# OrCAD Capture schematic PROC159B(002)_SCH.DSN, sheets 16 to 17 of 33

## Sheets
16 29. SOC-ADC & DAC INTERFACE: size C; title: SOC-ADC INTERFACE
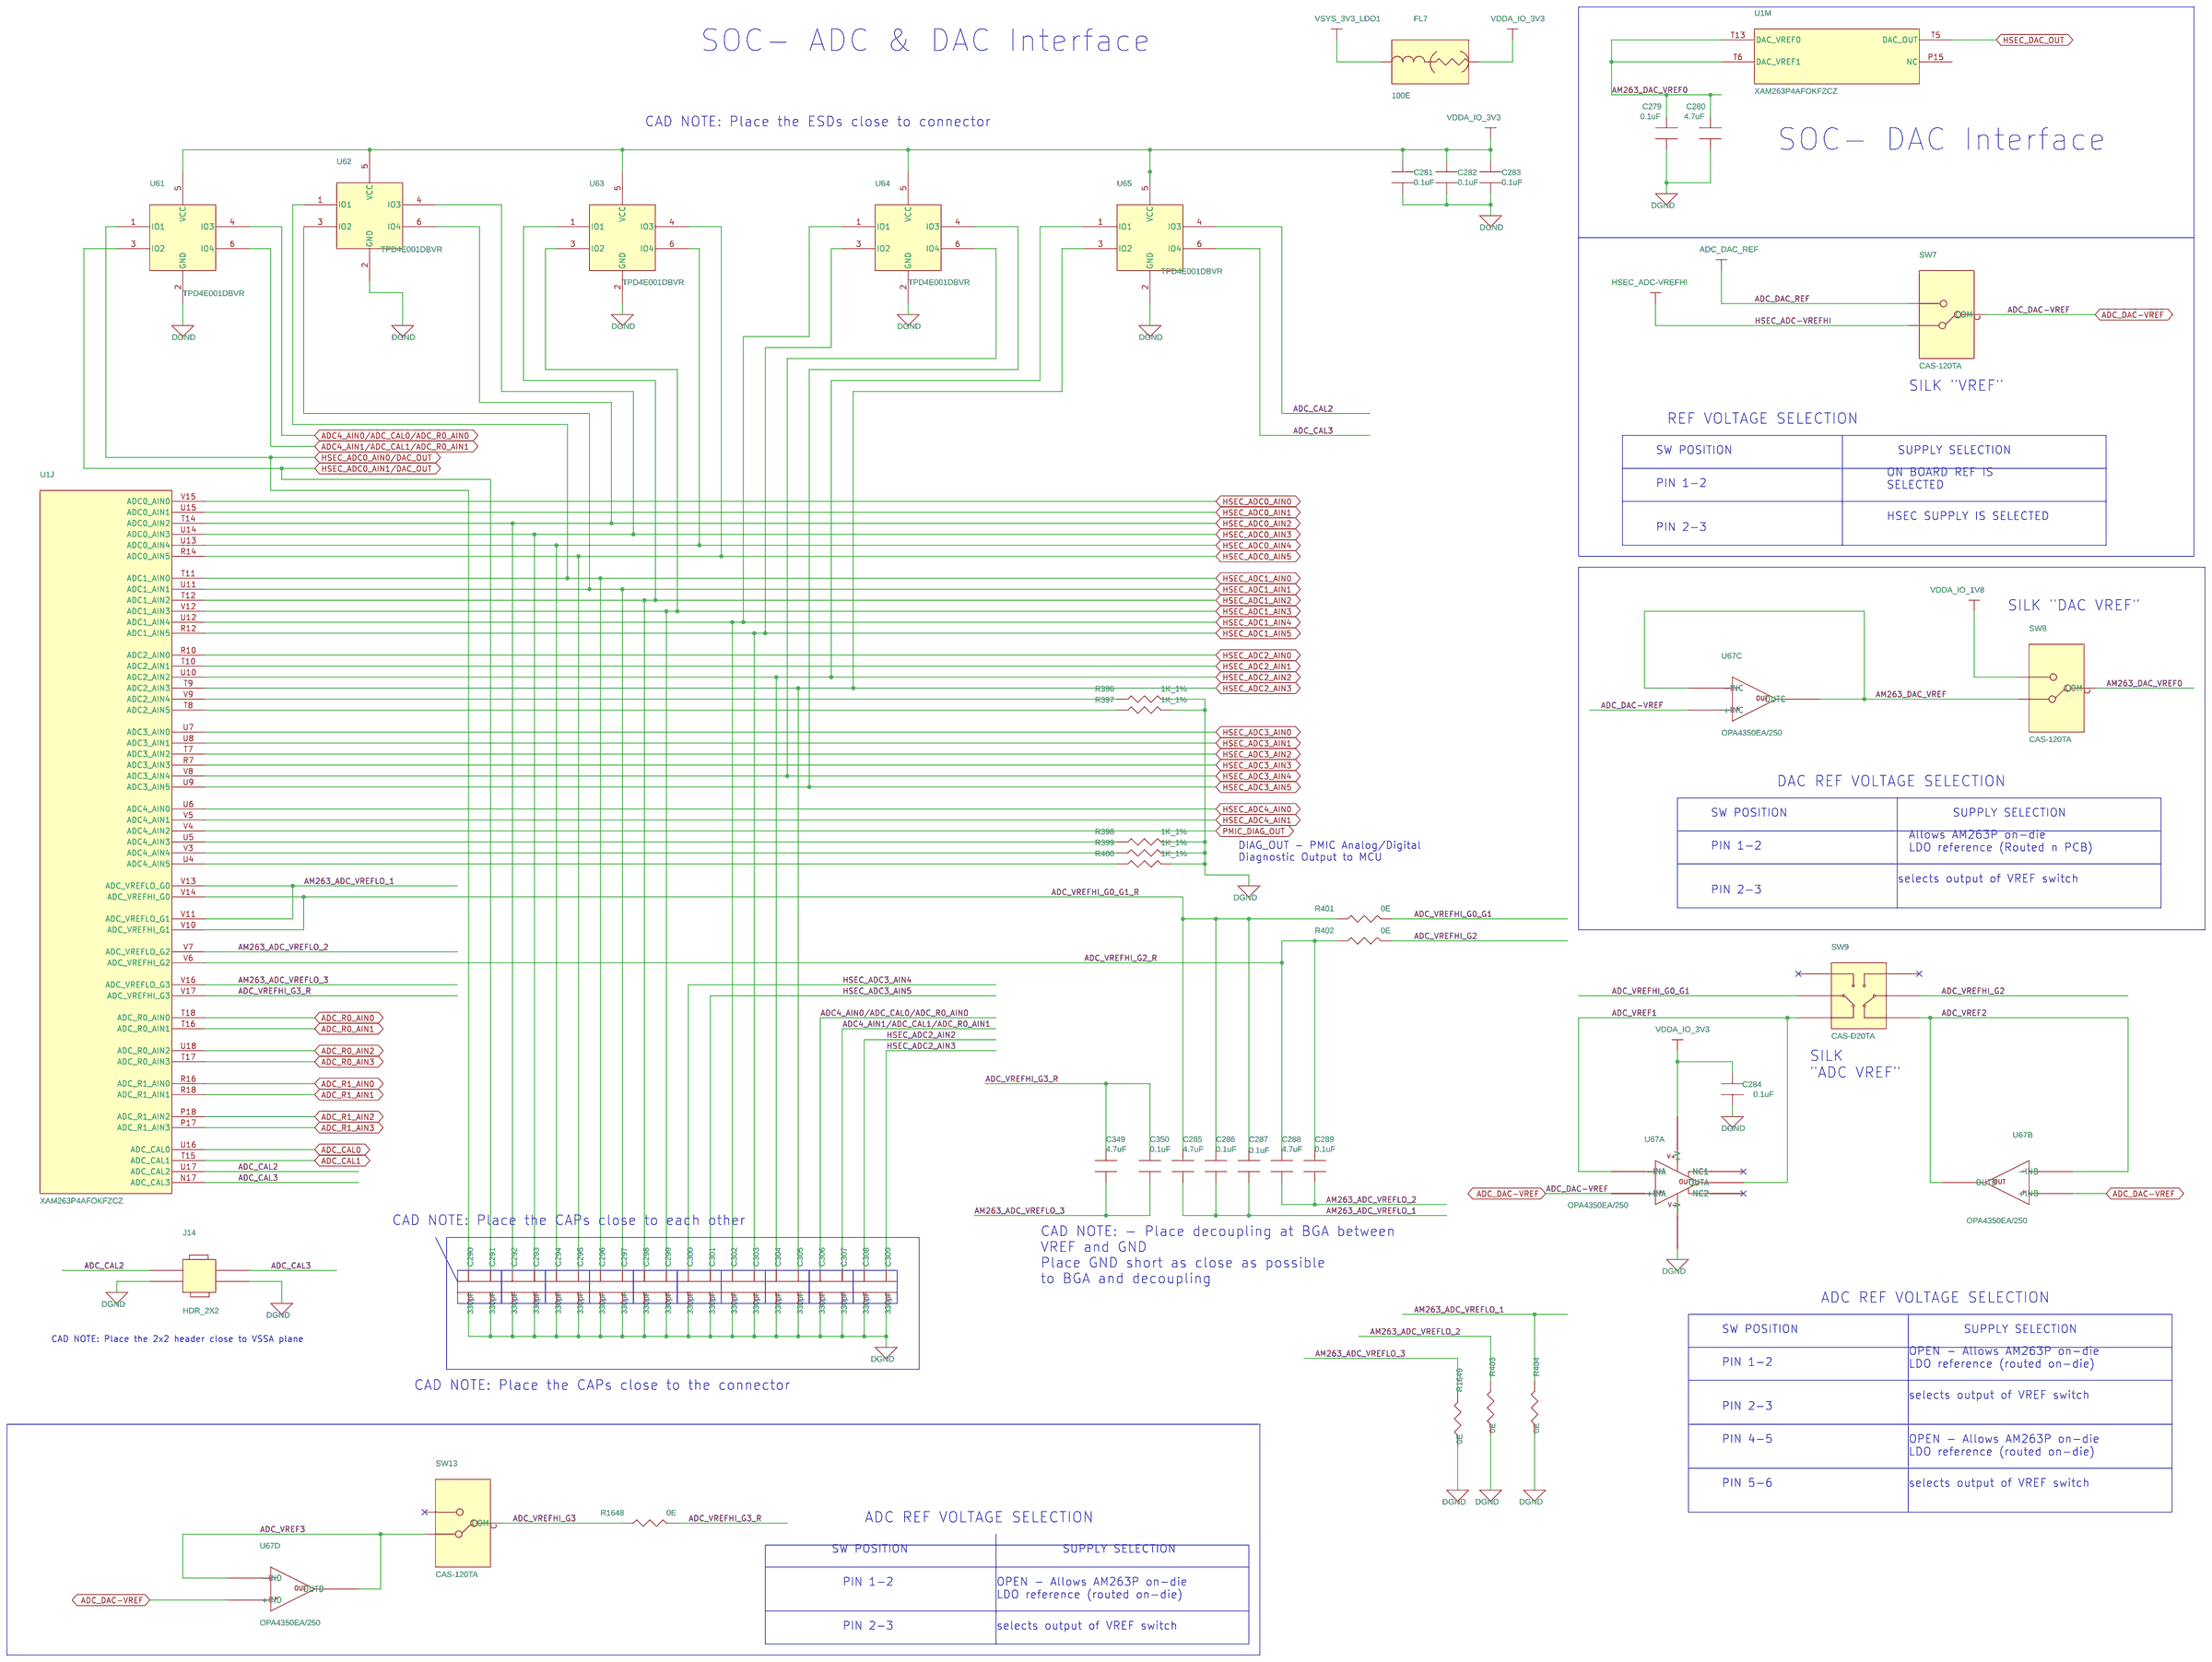
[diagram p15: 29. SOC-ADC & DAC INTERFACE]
17 26. XDS110 DEBUGGER: size C; title: XDS110 DEBUGGER
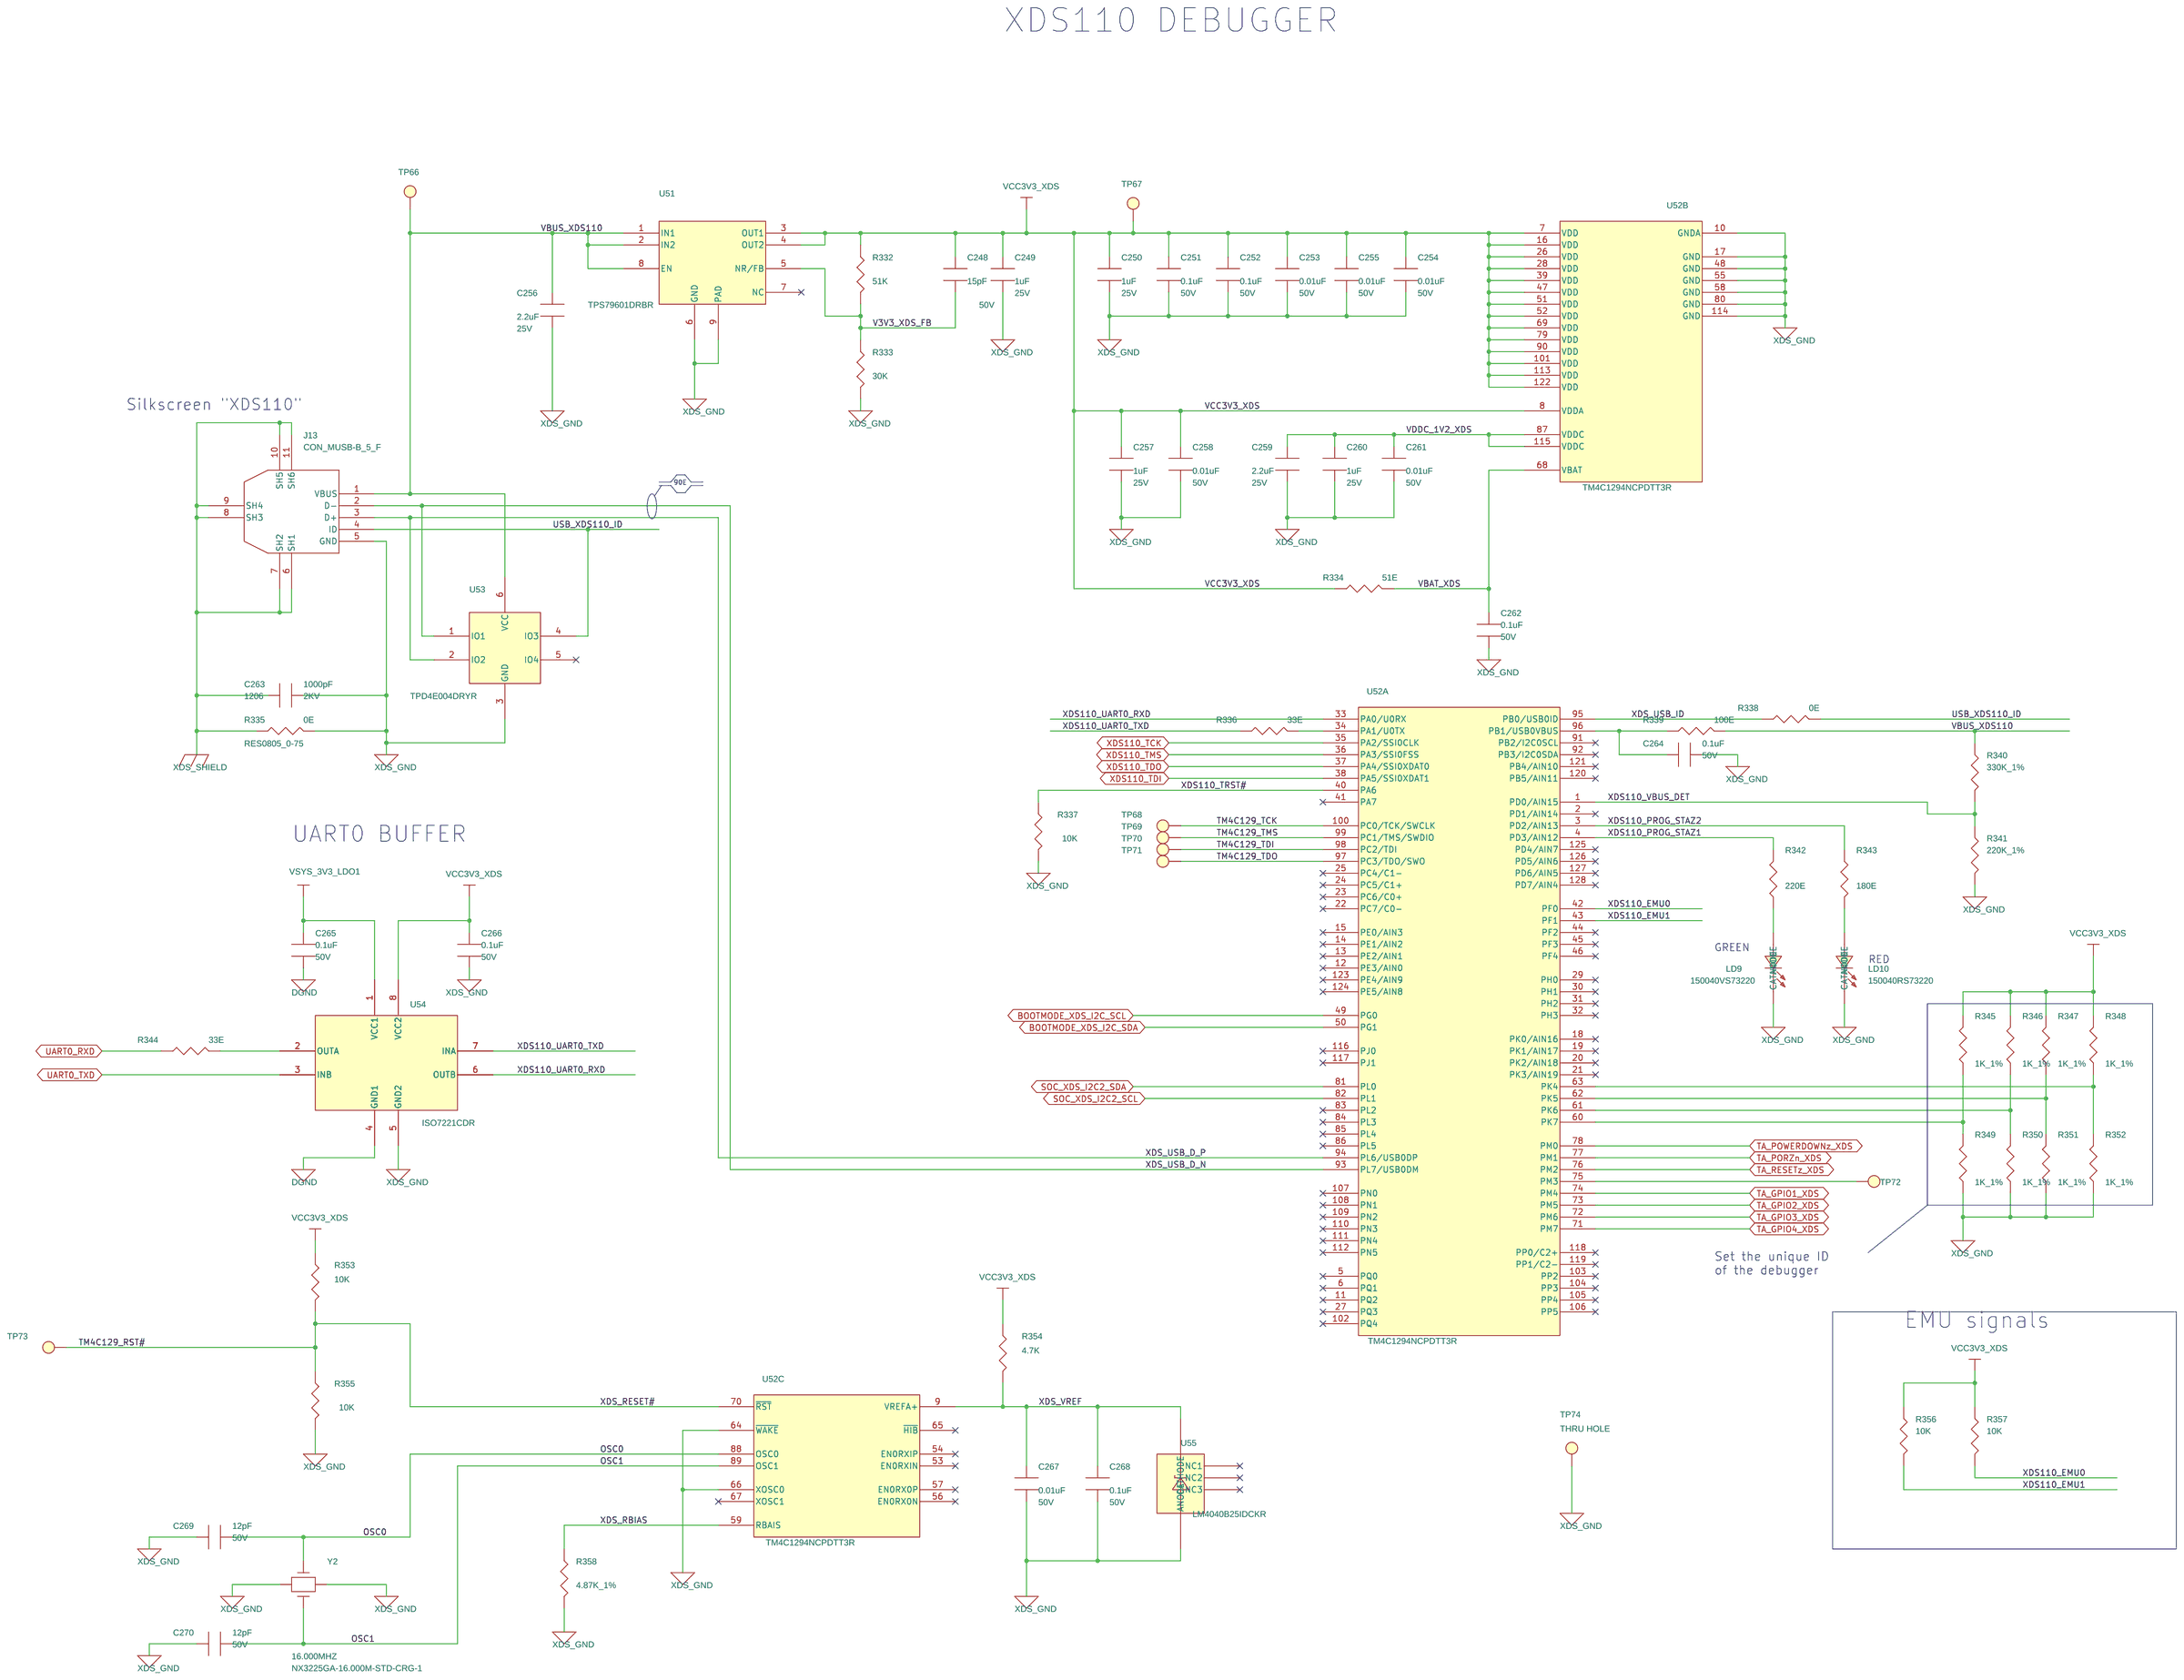
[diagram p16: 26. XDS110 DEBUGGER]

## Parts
sheet 19. SOC-ICSS DP8386(Indust)
U1  XAM263P4AFOKFZCZ  [BGA324_31-49_590X590_1-4]  (sections A,B,C,D,E,F,G,H,I,J,K,L,M)
sheet 26. XDS110 DEBUGGER
C248  15pF  [CAP0402_0-75]
C249  1uF  [CAP0402_0-75]
C250  1uF  [CAP0402_0-75]
C251  0.1uF  [CAP0402_0-75]
C252  0.1uF  [CAP0402_0-75]
C253  0.01uF  [CAP0402_0-75]
C254  0.01uF  [CAP0402_0-75]
C255  0.01uF  [CAP0402_0-75]
C256  2.2uF  [CAP0402_0-75]
C257  1uF  [CAP0402_0-75]
C258  0.01uF  [CAP0402_0-75]
C259  2.2uF  [CAP0402_0-75]
C260  1uF  [CAP0402_0-75]
C261  0.01uF  [CAP0402_0-75]
C262  0.1uF  [CAP0402_0-75]
C263  1000pF  [CAP1206_1-75]
C264  0.1uF  [CAP0402_0-75]
C265  0.1uF  [CAP0402_0-75]
C266  0.1uF  [CAP0402_0-75]
C267  0.01uF  [CAP0402_0-75]
C268  0.1uF  [CAP0402_0-75]
C269  12pF  [CAP0402_0-75]
C270  12pF  [CAP0402_0-75]
J13  CON_MUSB-B_5_F  [CON_USBB5_2013499-1_S_R_S_3]
LD9  150040VS73220  [LED_150040GS73220_40X20_SMD_0-4]
LD10  150040RS73220  [LED_150040GS73220_40X20_SMD_0-4]
R332  51K  [RES0402_0-5]
R333  30K  [RES0402_0-5]
R334  51E  [RES0402_0-5]
R335  0E  [RES0805_0-75]
R336  33E  [RES0402_0-5]
R337  10K  [RES0402_0-5]
R338  0E  [RES0402_0-5]
R339  100E  [RES0402_0-5]
R340  330K_1%  [RES0402_0-5]
R341  220K_1%  [RES0402_0-5]
R342  220E  [RES0402_0-5]
R343  180E  [RES0402_0-5]
R344  33E  [RES0402_0-5]
R345  1K_1%  [RES0402_0-5]
R346  1K_1%  [RES0402_0-5]
R347  1K_1%  [RES0402_0-5]
R348  1K_1%  [RES0402_0-5]
R349  1K_1%  [RES0402_0-5]
R350  1K_1%  [RES0402_0-5]
R351  1K_1%  [RES0402_0-5]
R352  1K_1%  [RES0402_0-5]
R353  10K  [RES0402_0-5]
R354  4.7K  [RES0402_0-5]
R355  10K  [RES0402_0-5]
R356  10K  [RES0402_0-5]
R357  10K  [RES0402_0-5]
R358  4.87K_1%  [RES0402_0-5]
TP66  TP40_SMD  [TP40_SMD]
TP67  TP40_SMD  [TP40_SMD]
TP68  TP40_SMD  [TP40_SMD]
TP69  TP40_SMD  [TP40_SMD]
TP70  TP40_SMD  [TP40_SMD]
TP71  TP40_SMD  [TP40_SMD]
TP72  TP40_SMD  [TP40_SMD]
TP73  TP40_SMD  [TP40_SMD]
TP74  THRU HOLE  [TP_40X65]
U51  TPS79601DRBR  [SON8_25-59_130X130_1]
U52  TM4C1294NCPDTT3R  [TQFP128_15-74_550X550_1-2]  (sections A,B,C)
U53  TPD4E004DRYR  [SON6_19-68_40X60_PB_0-6]
U54  ISO7221CDR  [SOIC8_1-8]
U55  LM4040B25IDCKR  [SC70-5_1-1]
Y2  16.000MHZ  [XTAL4_NX3225GA_130X100_SMD_0-9]
sheet 29. SOC-ADC & DAC INTERFACE
C279  0.1uF  [CAP0402_0-75]
C280  4.7uF  [CAP0402_0-75]
C281  0.1uF  [CAP0402_0-75]
C282  0.1uF  [CAP0402_0-75]
C283  0.1uF  [CAP0402_0-75]
C284  0.1uF  [CAP0402_0-75]
C285  4.7uF  [CAP0402_0-75]
C286  0.1uF  [CAP0201_0-5]
C287  0.1uF  [CAP0201_0-5]
C288  4.7uF  [CAP0402_0-75]
C289  0.1uF  [CAP0201_0-5]
C290  330pF  [CAP0402_0-75]
C291  330pF  [CAP0402_0-75]
C292  330pF  [CAP0402_0-75]
C293  330pF  [CAP0402_0-75]
C294  330pF  [CAP0402_0-75]
C295  330pF  [CAP0402_0-75]
C296  330pF  [CAP0402_0-75]
C297  330pF  [CAP0402_0-75]
C298  330pF  [CAP0402_0-75]
C299  330pF  [CAP0402_0-75]
C300  330pF  [CAP0402_0-75]
C301  330pF  [CAP0402_0-75]
C302  330pF  [CAP0402_0-75]
C303  330pF  [CAP0402_0-75]
C304  330pF  [CAP0402_0-75]
C305  330pF  [CAP0402_0-75]
C306  330pF  [CAP0402_0-75]
C307  330pF  [CAP0402_0-75]
C308  330pF  [CAP0402_0-75]
C309  330pF  [CAP0402_0-75]
C349  4.7uF  [CAP0402_0-75]
C350  0.1uF  [CAP0201_0-5]
FL7  100E  [EMIFIL_BLM18R_0603]
J14  HDR_2X2  [HDR_2X2_5-146256-2_S_T_8-3]
R396  1K_1%  [RES0402_0-5]
R397  1K_1%  [RES0402_0-5]
R398  1K_1%  [RES0402_0-5]
R399  1K_1%  [RES0402_0-5]
R400  1K_1%  [RES0402_0-5]
R401  0E  [RES0402_0-5]
R402  0E  [RES0402_0-5]
R403  0E  [RES0402_0-5]
R404  0E  [RES0402_0-5]
R1648  0E  [RES0402_0-5]
R1649  0E  [RES0402_0-5]
SW7  CAS-120TA  [SW3_CAS-120TA_215X100_SMD]
SW8  CAS-120TA  [SW3_CAS-120TA_215X100_SMD]
SW9  CAS-D20TA  [SW6_CAS-D20A_210X150_SMD]
SW13  CAS-120TA  [SW3_CAS-120TA_215X100_SMD]
U61  TPD4E001DBVR  [SOT23-6]
U62  TPD4E001DBVR  [SOT23-6]
U63  TPD4E001DBVR  [SOT23-6]
U64  TPD4E001DBVR  [SOT23-6]
U65  TPD4E001DBVR  [SOT23-6]
U67  OPA4350EA/250  [QSOP16_25_200X160_1-8]  (sections A,B,C,D)

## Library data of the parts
U1 = XAM263P4ASOKFZCZ_BGA324: IC SIP AM263P SoC BGA324; Chkd/date: PRADEEP/030124; Crtd /date: PRADEEP/030124; Custom_Duty: 15%; Customs_HS_Code: 85423100; Distributor_name: NA; Distributor_part_number: NA; Footprint Path: Y:\MIS_DATABASE\Library\ALTIUM_TOOL\PCB_FOOTPRINTS\Altium_Footprint_Lib.PcbLib; Height: 1.40MM; MECHANICAL 3D STEP FILE: NA; Mfr_name: TEXAS INSTRUMENTS; Mistral Part No: 141324010001; Package: BGA324; Part_type: ICS\DIGITAL\FPGA; Project: AM263P_CC; RoHS: RoHS; Temperature: NA; Tolerance: NA; Voltage: NA; Wattage: NA; Weight: NA; Datasheet: Y:\MIS_DATABASE\DATASHEETS\ICS\INTERFACE\ZCZ0324A.PDF
C248 = CAP: CAP CERAMIC 15pF 50V 1% HI-Q C0G(NP0) 0402; Automotive Alternate_mfr_name: TDK; Automotive Alternate_mfr_part_number: CGA2B2C0G1H150J050BA; Chkd/date: USMAN/120313; Crtd /date: USMAN/250213; Custom_Duty: 15%; Customs_HS_Code: 85322990; Direct Alternate_mfr_name: TDK; Direct Alternate_mfr_part_number: C1005NP01H150J050BA; Distributor_name: MOUSER; Distributor_part_number: 81-GJM1555C1H150FB1D; Footprint Path: Y:\MIS_DATABASE\Library\ALTIUM_TOOL\PCB_FOOTPRINTS\Altium_Footprint_Lib.PcbLib; Height: 0.55MM; Library Path: Y:\MIS_DATABASE\Library\ALTIUM_TOOL\SCHEMATICS_PARTS\MS_DISCRETE_Library.schlib; Mfr_name: MURATA; Mfr_part_number: GJM1555C1H150FB01D; Mistral Part No: 120013020008-R; Package: 0402; Part_type: CAPACITORS\CERAMIC; Project: TM2; RoHS: RoHS; Temperature: -55°C+125°C; Tolerance: 1%; Voltage: 50V; Wattage: NA; Weight: 6mg; Datasheet: Y:\MIS_DATABASE\DATASHEETS\CAPACITORS\MURATA-GXX-SER_NOV17.PDF
C249 C250 C257 C260 = CAP: CAP CERAMIC 1uF 25V 10% X6S 0402; Automotive Alternate_mfr_name: TAIYO YUDEN; Automotive Alternate_mfr_part_number: EMK105BJ105KVHF; Chkd/date: MANIRAJA/140518; Crtd /date: ALVY/140518; Custom_Duty: 15%; Customs_HS_Code: 85322990; Direct Alternate_mfr_name: YAGEO AMERICA; Direct Alternate_mfr_part_number: CC0402KRX5R7BB105; Distributor_name: DIGIKEY; Distributor_part_number: 490-10014-1-ND; Footprint Path: Y:\MIS_DATABASE\Library\ALTIUM_TOOL\PCB_FOOTPRINTS\Altium_Footprint_Lib.PcbLib; Height: 0.60MM; Library Path: Y:\MIS_DATABASE\Library\ALTIUM_TOOL\SCHEMATICS_PARTS\MS_DISCRETE_Library.schlib; Mfr_name: MURATA; Mfr_part_number: GRM155C81E105KE11D; Mistral Part No: 120018050004-R; Package: 0402; Part_type: CAPACITORS\CERAMIC; Project: TI_SVB_MAXWELL_DUT; RoHS: RoHS; Temperature: -55°C+105°C; Tolerance: 10%; Voltage: 25V; Wattage: NA; Weight: 6mg; Datasheet: Y:\MIS_DATABASE\DATASHEETS\CAPACITORS\GRM155C81E105KE11X.PDF
C251 C252 C262 C264-C266 C268 = CAP: CAP CERAMIC 0.1uF 50V 10% X7R 0402; Automotive Alternate_mfr_name: TDK; Automotive Alternate_mfr_part_number: CGA2B3X7R1H104K050BB; Chkd/date: MANIRAJA/261020; Crtd /date: ALVY/211020; Custom_Duty: 15%; Customs_HS_Code: 85322990; Direct Alternate_mfr_name: TDK; Direct Alternate_mfr_part_number: C1005X7R1H104K050BE; Distributor_name: DIGIKEY; Distributor_part_number: 490-10700-1-ND; Footprint Path: Y:\MIS_DATABASE\Library\ALTIUM_TOOL\PCB_FOOTPRINTS\Altium_Footprint_Lib.PcbLib; Height: 0.55MM; Library Path: Y:\MIS_DATABASE\Library\ALTIUM_TOOL\SCHEMATICS_PARTS\MS_DISCRETE_Library.schlib; Mfr_name: MURATA; Mfr_part_number: GRM155R71H104KE14D; Mistral Part No: 120011100014-R; Package: 0402; Part_type: CAPACITORS\CERAMIC; Project: J7_CP; RoHS: RoHS; Temperature: -55°C+125°C; Tolerance: 10%; Voltage: 50V; Wattage: NA; Weight: 3.1mg; Datasheet: Y:\MIS_DATABASE\DATASHEETS\CAPACITORS\GRM155R71H104KE14.PDF
C253-C255 C258 C261 C267 = CAP: CAP CERAMIC 0.01uF 50V 10% X7R 0402; Automotive Alternate_mfr_name: TDK; Automotive Alternate_mfr_part_number: CGA2B2X7R1E103K050BA; Chkd/date: MANIRAJA/280319; Crtd /date: MANIRAJA/280319; Custom_Duty: 15%; Customs_HS_Code: 85322990; Direct Alternate_mfr_name: YAGEO AMERICA; Direct Alternate_mfr_part_number: CC0402KRX7R8BB103; Distributor_name: DIGIKEY; Distributor_part_number: 490-4516-1-ND; Footprint Path: Y:\MIS_DATABASE\Library\ALTIUM_TOOL\PCB_FOOTPRINTS\Altium_Footprint_Lib.PcbLib; Height: 0.55MM; Library Path: Y:\MIS_DATABASE\Library\ALTIUM_TOOL\SCHEMATICS_PARTS\MS_DISCRETE_Library.schlib; Mfr_name: MURATA; Mfr_part_number: GRM155R71H103KA88D; Mistral Part No: 120009030025-R; Package: 0402; Part_type: CAPACITORS\CERAMIC; Project: G4_SVGA; RoHS: RoHS; Temperature: -55°C+125°C; Tolerance: 10%; Voltage: 50V; Wattage: NA; Weight: 0.65mg; Datasheet: Y:\MIS_DATABASE\DATASHEETS\CAPACITORS\GRM155R71H103KA88D.PDF
C256 C259 = CAP: CAP CERAMIC 2.2uF 25V 10% X5R 0402; Automotive Alternate_mfr_name: TAIYO YUDEN; Automotive Alternate_mfr_part_number: LMK105ABJ225MVHF; Chkd/date: ALVY/010721; Crtd /date: MANIRAJA/010721; Custom_Duty: 15%; Customs_HS_Code: 85322990; Direct Alternate_mfr_name: TDK; Direct Alternate_mfr_part_number: C1005X5R1A225K050BC; Distributor_name: DIGIKEY; Distributor_part_number: 490-12703-1-ND; Footprint Path: Y:\MIS_DATABASE\Library\ALTIUM_TOOL\PCB_FOOTPRINTS\Altium_Footprint_Lib.PcbLib; Height: 0.70MM; Library Path: Y:\MIS_DATABASE\Library\ALTIUM_TOOL\SCHEMATICS_PARTS\MS_DISCRETE_Library.schlib; Mfr_name: MURATA; Mfr_part_number: GRM155R61E225KE11D; Mistral Part No: 120015120001-R; Package: 0402; Part_type: CAPACITORS\CERAMIC; Project: TI_AM263X_CC; RoHS: RoHS; Temperature: -55°C+85°C; Tolerance: 10%; Voltage: 25V; Wattage: NA; Weight: 1.5mg; Datasheet: Y:\MIS_DATABASE\DATASHEETS\CAPACITORS\GRM155R61E225KE11.PDF
C263 = CAP: CAP CERAMIC 1000pF 2KV 10% X7R 1206; Chkd/date: SHREESHAIL/291106; Crtd /date: MAZHAR/281106; Custom_Duty: 15%; Customs_HS_Code: 85322990; Distributor_name: DIGIKEY; Distributor_part_number: 478-2956-1-ND; Footprint Path: Y:\MIS_DATABASE\Library\ALTIUM_TOOL\PCB_FOOTPRINTS\Altium_Footprint_Lib.PcbLib; Height: 1.52MM; Library Path: Y:\MIS_DATABASE\Library\ALTIUM_TOOL\SCHEMATICS_PARTS\MS_DISCRETE_Library.schlib; Mfr_name: AVX CORPORATION; Mfr_part_number: 1206GC102KAT1A; Mistral Part No: 120015080006-R; Package: 1206; Part_type: CAPACITORS\CERAMIC; Project: ADR1B; RoHS: RoHS; Temperature: -55°C+125°C; Tolerance: 10%; Voltage: 2KV; Wattage: NA; Weight: 16.2mg; Datasheet: Y:\MIS_DATABASE\DATASHEETS\CAPACITORS\AVX_HV-MLC.PDF
C269 C270 = CAP: CAP CERAMIC 12pF 50V 5% HI-Q C0G(NP0) 0402; Automotive Alternate_mfr_name: TDK; Automotive Alternate_mfr_part_number: CGA2B2C0G1H120J050BA; Chkd/date: MANIRAJA/020419; Crtd /date: MANIRAJA/020419; Custom_Duty: 15%; Customs_HS_Code: 85322990; Direct Alternate_mfr_name: SAMSUNG; Direct Alternate_mfr_part_number: CL05C120JB5NNNC; Distributor_name: DIGIKEY; Distributor_part_number: 490-3115-1-ND; Footprint Path: Y:\MIS_DATABASE\Library\ALTIUM_TOOL\PCB_FOOTPRINTS\Altium_Footprint_Lib.PcbLib; Height: 0.55MM; Library Path: Y:\MIS_DATABASE\Library\ALTIUM_TOOL\SCHEMATICS_PARTS\MS_DISCRETE_Library.schlib; Mfr_name: MURATA; Mfr_part_number: GJM1555C1H120JB01D; Mistral Part No: 120019040031-R; Package: 0402; Part_type: CAPACITORS\CERAMIC; Project: EPDA_CORE; RoHS: RoHS; Temperature: -55°C+125°C; Tolerance: 5%; Voltage: 50V; Wattage: NA; Weight: 0.65mg; Datasheet: Y:\MIS_DATABASE\DATASHEETS\CAPACITORS\GJM1555C1H120JB01.PDF
J13 = CON_USB_MINI-B11: CON MICRO USB-B TYPE 5POS FEMALE RT SMD; Chkd/date: MANIRAJA/021220; Crtd /date: ALVY/021220; Custom_Duty: 24%; Customs_HS_Code: 85369090; Distributor_name: DIGIKEY; Distributor_part_number: A107962CT-ND; Footprint Path: Y:\MIS_DATABASE\Library\ALTIUM_TOOL\PCB_FOOTPRINTS\Altium_Footprint_Lib.PcbLib; Height: 3.00MM; Library Path: Y:\MIS_DATABASE\Library\ALTIUM_TOOL\SCHEMATICS_PARTS\MS_CONNECTOR_Library.schlib; Mfr_name: TE CONNECTIVITY; Mfr_part_number: 2013499-1; Mistral Part No: 150020120001-R; Package: SMD; Part_type: CONNECTOR\USB; Project: VEETECH_SENSOR_BADGE; RoHS: RoHS; Temperature: -30°C+85°C; Tolerance: NA; Voltage: NA; Wattage: NA; Weight: 624mg; Datasheet: Y:\MIS_DATABASE\DATASHEETS\CONNECTORS\2013499.PDF
LD9 = DIODE_LED: DIODE LED BRIGHT GREEN SMD; Chkd/date: MANIRAJA/261120; Crtd /date: ALVY/261120; Custom_Duty: 24%; Customs_HS_Code: 85439000; Distributor_name: DIGIKEY; Distributor_part_number: 732-13425-1-ND; Footprint Path: Y:\MIS_DATABASE\Library\ALTIUM_TOOL\PCB_FOOTPRINTS\Altium_Footprint_Lib.PcbLib; Height: 0.35MM; Library Path: Y:\MIS_DATABASE\Library\ALTIUM_TOOL\SCHEMATICS_PARTS\MS_OPTO_Library.schlib; Mfr_name: WURTH ELECTRONIK; Mistral Part No: 130020110071-R; Package: SMD; Part_type: OPTO\LED; Project: AM64X_SKEVM; RoHS: RoHS; Temperature: -40°C+85°C; Tolerance: NA; Voltage: NA; Wattage: NA; Weight: 29.3mg; Datasheet: Y:\MIS_DATABASE\DATASHEETS\DISCRETES\LEDS\150040VS73220.PDF
LD10 = DIODE_LED: DIODE LED RED SMD; Chkd/date: MANIRAJA/100920; Crtd /date: ALVY/100920; Custom_Duty: 24%; Customs_HS_Code: 85439000; Distributor_name: DIGIKEY; Distributor_part_number: 732-13422-1-ND; Footprint Path: Y:\MIS_DATABASE\Library\ALTIUM_TOOL\PCB_FOOTPRINTS\Altium_Footprint_Lib.PcbLib; Height: 0.35MM; Library Path: Y:\MIS_DATABASE\Library\ALTIUM_TOOL\SCHEMATICS_PARTS\MS_OPTO_Library.schlib; Mfr_name: WURTH ELECTRONICS; Mistral Part No: 130020090020-R; Package: SMD; Part_type: OPTO\LED; Project: AM64X_SKEVM; RoHS: RoHS; Temperature: -40°C+85°C; Tolerance: NA; Voltage: NA; Wattage: NA; Weight: 29.3mg; Datasheet: Y:\MIS_DATABASE\DATASHEETS\DISCRETES\LEDS\150040RS73220.PDF
R332 = RESISTOR: RES 51K 1/16W 5% 0402; Chkd/date: MANIRAJA/230817; Crtd /date: MANIRAJA/230817; Custom_Duty: 15%; Customs_HS_Code: 85332119; Distributor_name: DIGIKEY; Distributor_part_number: 541-51KJCT-ND; Footprint Path: Y:\MIS_DATABASE\Library\ALTIUM_TOOL\PCB_FOOTPRINTS\Altium_Footprint_Lib.PcbLib; Height: 0.40MM; Library Path: Y:\MIS_DATABASE\Library\ALTIUM_TOOL\SCHEMATICS_PARTS\MS_DISCRETE_Library.schlib; Mfr_name: VISHAY; Mfr_part_number: CRCW040251K0JNED; Mistral Part No: 110009030966-R; Package: 0402; Part_type: RESISTORS\FIXED; Project: TI_MAXIE_CPB; RoHS: RoHS; Temperature: -55°C+155°C; Tolerance: 5%; Voltage: NA; Wattage: 1/16W; Weight: 0.65mg; Datasheet: Y:\MIS_DATABASE\DATASHEETS\RESISTORS\CRCW0603.PDF
R333 = RESISTOR: RES 30K 1/16W 5% 0402; Chkd/date: MANIRAJA/230817; Crtd /date: MANIRAJA/230817; Custom_Duty: 15%; Customs_HS_Code: 85332119; Distributor_name: DIGIKEY; Distributor_part_number: 541-30KJCT-ND; Footprint Path: Y:\MIS_DATABASE\Library\ALTIUM_TOOL\PCB_FOOTPRINTS\Altium_Footprint_Lib.PcbLib; Height: 0.40MM; Library Path: Y:\MIS_DATABASE\Library\ALTIUM_TOOL\SCHEMATICS_PARTS\MS_DISCRETE_Library.schlib; Mfr_name: VISHAY; Mfr_part_number: CRCW040230K0JNED; Mistral Part No: 110017080023-R; Package: 0402; Part_type: RESISTORS\FIXED; Project: TI_MAXIE_CPB; RoHS: RoHS; Temperature: -55°C+155°C; Tolerance: 5%; Voltage: NA; Wattage: 1/16W; Weight: 0.65mg; Datasheet: Y:\MIS_DATABASE\DATASHEETS\RESISTORS\CRCW0603.PDF
R334 = RESISTOR: RES 51E 1/10W 5% 0402; Chkd/date: VASANTHA/291216; Crtd /date: MAZHAR/120505; Custom_Duty: 15%; Customs_HS_Code: 85332119; Distributor_name: DIGIKEY; Distributor_part_number: P51JCT-ND; Footprint Path: Y:\MIS_DATABASE\Library\ALTIUM_TOOL\PCB_FOOTPRINTS\Altium_Footprint_Lib.PcbLib; Height: 0.40MM; Library Path: Y:\MIS_DATABASE\Library\ALTIUM_TOOL\SCHEMATICS_PARTS\MS_DISCRETE_Library.schlib; Mfr_name: PANASONIC-ECG; Mfr_part_number: ERJ-2GEJ510X; Mistral Part No: 110009030962-R; Package: 0402; Part_type: RESISTORS\FIXED; Project: CTP02_REVA_BASE; RoHS: RoHS; Temperature: -55°C+155°C; Tolerance: 5%; Voltage: NA; Wattage: 1/10W; Weight: 0.8mg; Datasheet: Y:\MIS_DATABASE\DATASHEETS\RESISTORS\PAN-ERJSER_NOV17.PDF
R335 = RESISTOR: RES 0E 1/8W 5% 0805; Chkd/date: VASANTHA/130416; Crtd /date: JEBRAN/020316; Custom_Duty: 15%; Customs_HS_Code: 85332119; Distributor_name: DIGIKEY; Distributor_part_number: 311-0.0ARCT-ND; Footprint Path: Y:\MIS_DATABASE\Library\ALTIUM_TOOL\PCB_FOOTPRINTS\Altium_Footprint_Lib.PcbLib; Height: 0.60MM; Library Path: Y:\MIS_DATABASE\Library\ALTIUM_TOOL\SCHEMATICS_PARTS\MS_DISCRETE_Library.schlib; Mfr_name: YAGEO AMERICA; Mfr_part_number: RC0805JR-070RL; Mistral Part No: 110009030074-R; Package: 0805; Part_type: RESISTORS\FIXED; Project: ZK_BIOMETRIC; RoHS: RoHS; Temperature: -55°C+155°C; Tolerance: 5%; Voltage: NA; Wattage: 1/8W; Weight: 5.5mg; Datasheet: Y:\MIS_DATABASE\DATASHEETS\RESISTORS\RCXXXXL-SER_MAR18.PDF
R336 R344 = RESISTOR: RES 33E 1/10W 5% 0402; Chkd/date: VASANTHA/201216; Crtd /date: GEETHA/190406; Custom_Duty: 15%; Customs_HS_Code: 85332119; Distributor_name: DIGIKEY; Distributor_part_number: P33JCT-ND; Footprint Path: Y:\MIS_DATABASE\Library\ALTIUM_TOOL\PCB_FOOTPRINTS\Altium_Footprint_Lib.PcbLib; Height: 0.40MM; Library Path: Y:\MIS_DATABASE\Library\ALTIUM_TOOL\SCHEMATICS_PARTS\MS_DISCRETE_Library.schlib; Mfr_name: PANASONIC-ECG; Mfr_part_number: ERJ-2GEJ330X; Mistral Part No: 110009030699-R; Package: 0402; Part_type: RESISTORS\FIXED; Project: RED EYE; RoHS: RoHS; Temperature: -55°C+155°C; Tolerance: 5%; Voltage: NA; Wattage: 1/10W; Weight: 0.8mg; Datasheet: Y:\MIS_DATABASE\DATASHEETS\RESISTORS\PAN-ERJSER_NOV17.PDF
R337 R355-R357 = RESISTOR: RES 10K 1/16W 5% 0402; Assembly_Instruction: DNI; Chkd/date: VASANTHA/061216; Crtd /date: MAZHAR/230805; Custom_Duty: 15%; Customs_HS_Code: 85332119; Distributor_name: DIGIKEY; Distributor_part_number: 311-10KJRCT-ND; Footprint Path: Y:\MIS_DATABASE\Library\ALTIUM_TOOL\PCB_FOOTPRINTS\Altium_Footprint_Lib.PcbLib; Height: 0.40MM; Library Path: Y:\MIS_DATABASE\Library\ALTIUM_TOOL\SCHEMATICS_PARTS\MS_DISCRETE_Library.schlib; Mfr_name: YAGEO AMERICA; Mfr_part_number: RC0402JR-0710KL; Mistral Part No: 110011060021-R; Package: 0402; Part_type: RESISTORS\FIXED; Project: HSE; RoHS: RoHS; Temperature: -55°C+155°C; Tolerance: 5%; Voltage: NA; Wattage: 1/16W; Weight: 0.65mg; Datasheet: Y:\MIS_DATABASE\DATASHEETS\RESISTORS\RCXXXXL-SER_MAR18.PDF
R338 = RESISTOR: RES 0E 1/10W JUMPER 0402; Assembly_Instruction: DNI; Chkd/date: VASANTHA/061216; Crtd /date: NAVEED/201014; Custom_Duty: 15%; Customs_HS_Code: 85332119; Distributor_name: DIGIKEY; Distributor_part_number: P0.0JCT-ND; Footprint Path: Y:\MIS_DATABASE\Library\ALTIUM_TOOL\PCB_FOOTPRINTS\Altium_Footprint_Lib.PcbLib; Height: 0.40MM; IBISSP_MODLES: VALUE REPEATING 2 TIME; Library Path: Y:\MIS_DATABASE\Library\ALTIUM_TOOL\SCHEMATICS_PARTS\MS_DISCRETE_Library.schlib; Mfr_name: PANASONIC-ECG; Mfr_part_number: ERJ-2GE0R00X; Mistral Part No: 110018030052-R; Package: 0402; Part_type: RESISTORS\FIXED; Project: AEGIS POM; RoHS: RoHS; Temperature: -55°C+155°C; Tolerance: NA; Voltage: NA; Wattage: 1/10W; Weight: 0.8mg; Datasheet: Y:\MIS_DATABASE\DATASHEETS\RESISTORS\PAN-ERJSER_NOV17.PDF
R339 = RESISTOR: RES 100E 1/10W 1% 0402; Chkd/date: ALVY/230621; Crtd /date: ALVY/230621; Custom_Duty: 15%; Customs_HS_Code: 85332119; Distributor_name: DIGIKEY; Distributor_part_number: 10-ERJ-U02F1000XCT-ND; Footprint Path: Y:\MIS_DATABASE\Library\ALTIUM_TOOL\PCB_FOOTPRINTS\Altium_Footprint_Lib.PcbLib; Height: 0.40MM; Library Path: Y:\MIS_DATABASE\Library\ALTIUM_TOOL\SCHEMATICS_PARTS\MS_DISCRETE_Library.schlib; Mfr_name: PANASONIC-ECG; Mfr_part_number: ERJ-U02F1000X; Mistral Part No: 110018020036-R; Package: 0402; Part_type: RESISTORS\FIXED; Project: AM263x_CC; RoHS: RoHS; Temperature: -55°C+155°C; Tolerance: 1%; Voltage: NA; Wattage: 1/10W; Weight: 0.8mg; Datasheet: Y:\MIS_DATABASE\DATASHEETS\RESISTORS\ERJ-U0_S0.PDF
R340 = RESISTOR: RES 330K 1/16W 1% 0402; Chkd/date: MANIRAJA/230817; Crtd /date: MANIRAJA/230817; Custom_Duty: 15%; Customs_HS_Code: 85332119; Distributor_name: DIGIKEY; Distributor_part_number: 541-330KLCT-ND; Footprint Path: Y:\MIS_DATABASE\Library\ALTIUM_TOOL\PCB_FOOTPRINTS\Altium_Footprint_Lib.PcbLib; Height: 0.40MM; Library Path: Y:\MIS_DATABASE\Library\ALTIUM_TOOL\SCHEMATICS_PARTS\MS_DISCRETE_Library.schlib; Mfr_name: VISHAY; Mfr_part_number: CRCW0402330KFKED; Mistral Part No: 110017080024-R; Package: 0402; Part_type: RESISTORS\FIXED; Project: TI_MAXIE_CPB; RoHS: RoHS; Temperature: -55°C+155°C; Tolerance: 1%; Voltage: NA; Wattage: 1/16W; Weight: 0.65mg; Datasheet: Y:\MIS_DATABASE\DATASHEETS\RESISTORS\CRCW0603.PDF
R341 = RESISTOR: RES 220K 1/16W 1% 0402; Chkd/date: MANIRAJA/230817; Crtd /date: MANIRAJA/230817; Custom_Duty: 15%; Customs_HS_Code: 85332119; Distributor_name: DIGIKEY; Distributor_part_number: 541-220KLCT-ND; Footprint Path: Y:\MIS_DATABASE\Library\ALTIUM_TOOL\PCB_FOOTPRINTS\Altium_Footprint_Lib.PcbLib; Height: 0.40MM; Library Path: Y:\MIS_DATABASE\Library\ALTIUM_TOOL\SCHEMATICS_PARTS\MS_DISCRETE_Library.schlib; Mfr_name: VISHAY; Mfr_part_number: CRCW0402220KFKED; Mistral Part No: 110017080025-R; Package: 0402; Part_type: RESISTORS\FIXED; Project: TI_MAXIE_CPB; RoHS: RoHS; Temperature: -55°C+155°C; Tolerance: 1%; Voltage: NA; Wattage: 1/16W; Weight: 0.65mg; Datasheet: Y:\MIS_DATABASE\DATASHEETS\RESISTORS\CRCW0603.PDF
R342 = RESISTOR: RES 220E 1/10W 5% 0402; Chkd/date: VASANTHA/291216; Crtd /date: GEETHA/260406; Custom_Duty: 15%; Customs_HS_Code: 85332119; Distributor_name: DIGIKEY; Distributor_part_number: P220JCT-ND; Footprint Path: Y:\MIS_DATABASE\Library\ALTIUM_TOOL\PCB_FOOTPRINTS\Altium_Footprint_Lib.PcbLib; Height: 0.40MM; Library Path: Y:\MIS_DATABASE\Library\ALTIUM_TOOL\SCHEMATICS_PARTS\MS_DISCRETE_Library.schlib; Mfr_name: PANASONIC-ECG; Mfr_part_number: ERJ-2GEJ221X; Mistral Part No: 110009030506-R; Package: 0402; Part_type: RESISTORS\FIXED; Project: RED EYE; RoHS: RoHS; Temperature: -55°C+155°C; Tolerance: 5%; Voltage: NA; Wattage: 1/10W; Weight: 0.8mg; Datasheet: Y:\MIS_DATABASE\DATASHEETS\RESISTORS\PAN-ERJSER_NOV17.PDF
R343 = RESISTOR: RES 180E 1/10W 5% 0402; Chkd/date: MAZHAR/150709; Crtd /date: GEETHA/280406; Custom_Duty: 15%; Customs_HS_Code: 85332119; Distributor_name: DIGIKEY; Distributor_part_number: P180JCT-ND; Footprint Path: Y:\MIS_DATABASE\Library\ALTIUM_TOOL\PCB_FOOTPRINTS\Altium_Footprint_Lib.PcbLib; Height: 0.40MM; Library Path: Y:\MIS_DATABASE\Library\ALTIUM_TOOL\SCHEMATICS_PARTS\MS_DISCRETE_Library.schlib; Mfr_name: PANASONIC-ECG; Mfr_part_number: ERJ-2GEJ181X; Mistral Part No: 110009030371-R; Package: 0402; Part_type: RESISTORS\FIXED; Project: RED EYE; RoHS: RoHS; Temperature: -55°C+155°C; Tolerance: 5%; Voltage: NA; Wattage: 1/10W; Weight: 0.8mg; Datasheet: Y:\MIS_DATABASE\DATASHEETS\RESISTORS\PAN-ERJSER_NOV17.PDF
R345-R348 R396-R400 = RESISTOR: RES 1K 1/10W 1% 0402; Chkd/date: VASANTHA/281216; Crtd /date: MAZHAR/150506; Custom_Duty: 15%; Customs_HS_Code: 85332119; Distributor_name: DIGIKEY; Distributor_part_number: P1.00KLCT-ND; Footprint Path: Y:\MIS_DATABASE\Library\ALTIUM_TOOL\PCB_FOOTPRINTS\Altium_Footprint_Lib.PcbLib; Height: 0.40MM; Library Path: Y:\MIS_DATABASE\Library\ALTIUM_TOOL\SCHEMATICS_PARTS\MS_DISCRETE_Library.schlib; Mfr_name: PANASONIC-ECG; Mfr_part_number: ERJ-2RKF1001X; Mistral Part No: 110009030411-R; Package: 0402; Part_type: RESISTORS\FIXED; Project: VOCERA; RoHS: RoHS; Temperature: -55°C+155°C; Tolerance: 1%; Voltage: NA; Wattage: 1/10W; Weight: 0.8mg; Datasheet: Y:\MIS_DATABASE\DATASHEETS\RESISTORS\PAN-ERJSER_NOV17.PDF
R349-R352 = RESISTOR: RES 1K 1/10W 1% 0402; Assembly_Instruction: DNI; Chkd/date: VASANTHA/281216; Crtd /date: MAZHAR/150506; Custom_Duty: 15%; Customs_HS_Code: 85332119; Distributor_name: DIGIKEY; Distributor_part_number: P1.00KLCT-ND; Footprint Path: Y:\MIS_DATABASE\Library\ALTIUM_TOOL\PCB_FOOTPRINTS\Altium_Footprint_Lib.PcbLib; Height: 0.40MM; Library Path: Y:\MIS_DATABASE\Library\ALTIUM_TOOL\SCHEMATICS_PARTS\MS_DISCRETE_Library.schlib; Mfr_name: PANASONIC-ECG; Mfr_part_number: ERJ-2RKF1001X; Mistral Part No: 110009030411-R; Package: 0402; Part_type: RESISTORS\FIXED; Project: VOCERA; RoHS: RoHS; Temperature: -55°C+155°C; Tolerance: 1%; Voltage: NA; Wattage: 1/10W; Weight: 0.8mg; Datasheet: Y:\MIS_DATABASE\DATASHEETS\RESISTORS\PAN-ERJSER_NOV17.PDF
R353 = RESISTOR: RES 10K 1/16W 5% 0402; Chkd/date: VASANTHA/061216; Crtd /date: MAZHAR/230805; Custom_Duty: 15%; Customs_HS_Code: 85332119; Distributor_name: DIGIKEY; Distributor_part_number: 311-10KJRCT-ND; Footprint Path: Y:\MIS_DATABASE\Library\ALTIUM_TOOL\PCB_FOOTPRINTS\Altium_Footprint_Lib.PcbLib; Height: 0.40MM; Library Path: Y:\MIS_DATABASE\Library\ALTIUM_TOOL\SCHEMATICS_PARTS\MS_DISCRETE_Library.schlib; Mfr_name: YAGEO AMERICA; Mfr_part_number: RC0402JR-0710KL; Mistral Part No: 110011060021-R; Package: 0402; Part_type: RESISTORS\FIXED; Project: HSE; RoHS: RoHS; Temperature: -55°C+155°C; Tolerance: 5%; Voltage: NA; Wattage: 1/16W; Weight: 0.65mg; Datasheet: Y:\MIS_DATABASE\DATASHEETS\RESISTORS\RCXXXXL-SER_MAR18.PDF
R354 = RESISTOR: RES 4.7K 1/16W 5% 0402; Chkd/date: VASANTHA/130516; Crtd /date: VASANTHA/130516; Custom_Duty: 15%; Customs_HS_Code: 85332119; Distributor_name: DIGIKEY; Distributor_part_number: 311-4.7KJRCT-ND; Footprint Path: Y:\MIS_DATABASE\Library\ALTIUM_TOOL\PCB_FOOTPRINTS\Altium_Footprint_Lib.PcbLib; Height: 0.40MM; Library Path: Y:\MIS_DATABASE\Library\ALTIUM_TOOL\SCHEMATICS_PARTS\MS_DISCRETE_Library.schlib; Mfr_name: YAGEO AMERICA; Mfr_part_number: RC0402JR-074K7L; Mistral Part No: 110011060001-R; Package: 0402; Part_type: RESISTORS\FIXED; Project: TMDXCSK368; RoHS: RoHS; Temperature: -55°C+155°C; Tolerance: 5%; Voltage: NA; Wattage: 1/16W; Weight: 0.65mg; Datasheet: Y:\MIS_DATABASE\DATASHEETS\RESISTORS\RCXXXXL-SER_MAR18.PDF
R358 = RESISTOR: RES 4.87K 1/10W 1% 0402; Chkd/date: MAZHAR/150709; Crtd /date: USMAN/150109; Custom_Duty: 15%; Customs_HS_Code: 85332119; Distributor_name: DIGIKEY; Distributor_part_number: P4.87KLCT-ND; Footprint Path: Y:\MIS_DATABASE\Library\ALTIUM_TOOL\PCB_FOOTPRINTS\Altium_Footprint_Lib.PcbLib; Height: 0.40MM; Library Path: Y:\MIS_DATABASE\Library\ALTIUM_TOOL\SCHEMATICS_PARTS\MS_DISCRETE_Library.schlib; Mfr_name: PANASONIC-ECG; Mfr_part_number: ERJ-2RKF4871X; Mistral Part No: 110009030803-R; Package: 0402; Part_type: RESISTORS\FIXED; Project: BSN-II; RoHS: RoHS; Temperature: -55°C+155°C; Tolerance: 1%; Voltage: NA; Wattage: 1/10W; Weight: 0.8mg; Datasheet: Y:\MIS_DATABASE\DATASHEETS\RESISTORS\PAN-ERJSER_NOV17.PDF
TP66-TP73 = TESTPOINT: TESTPOINT CIR 40 SMD; Chkd/date: MAZHAR/190505; Crtd /date: MAZHAR/190505; Distributor_name: NA; Distributor_part_number: NA; Footprint Path: Y:\MIS_DATABASE\Library\ALTIUM_TOOL\PCB_FOOTPRINTS\Altium_Footprint_Lib.PcbLib; Height: NA; Library Path: Y:\MIS_DATABASE\Library\ALTIUM_TOOL\SCHEMATICS_PARTS\MS_DISCRETE_Library.schlib; MECHANICAL 3D STEP FILE: NA; Mfr_name: LOCAL; Mistral Part No: 130009030933; Package: SMD; Project: RAINIER-3; RoHS: NA; Temperature: NA; Tolerance: NA; Voltage: NA; Wattage: NA; Weight: NA; Datasheet: NA
TP74 = TESTPOINT: TESTPOINT 1.0MM DRILL PTH; Chkd/date: MAZHAR/271211; Crtd /date: SHREESHAIL/041005; Distributor_name: NA; Distributor_part_number: NA; Height: NA; Mfr_name: LOCAL; Mistral Part No: 130009030938; Package: THRU-HOLE; Project: HSE; Datasheet: NA
U51 = TPS79601DRBR_SON8: IC 1A HIGH PSRR RF ADJ LDO LINEAR REGULATOR SON8; Chkd/date: MANIRAJA/030518; Crtd /date: MAZHAR/280809; Custom_Duty: 15%; Customs_HS_Code: 85423100; Distributor_name: DIGIKEY; Distributor_part_number: 296-23107-1-ND; Footprint Path: Y:\MIS_DATABASE\Library\ALTIUM_TOOL\PCB_FOOTPRINTS\Altium_Footprint_Lib.PcbLib; Height: 1.00MM; Library Path: Y:\MIS_DATABASE\Library\ALTIUM_TOOL\SCHEMATICS_PARTS\MS_MISCPOWER_Library.schlib; Mfr_name: TEXAS INSTRUMENTS; Mistral Part No: 142009080012-R; Package: SON8; Part_type: ICS\POWER\VOLTAGE REGULATOR; Project: DIO_TXRX; RoHS: RoHS; Temperature: -40°C+125°C; Tolerance: NA; Voltage: NA; Wattage: NA; Weight: 24mg; Datasheet: Y:\MIS_DATABASE\DATASHEETS\MISC\REGULATORS\TPS796XX.PDF
U52 = TM4C1294NCPDTT3R_TQFP128: IC 32-BIT MICROCONTROLLER WITH 1MB FLASH TQFP128; Chkd/date: MANIRAJA/220817; Crtd /date: MANIRAJA/220817; Custom_Duty: 15%; Customs_HS_Code: 85423100; Distributor_name: DIGIKEY; Distributor_part_number: TM4C1294NCPDTT3R-ND; Height: 1.20MM; Mfr_name: TEXAS INSTRUMENTS; Mistral Part No: 141217080002-R; Package: TQF9128; Part_type: ICS\DIGITAL\MICROCONTROLLER; Project: TI_MAXIE_CPB; RoHS: RoHS; Temperature: -40°C+105°C; Tolerance: NA; Voltage: NA; Wattage: NA; Weight: 503.5mg; Datasheet: Y:\MIS_DATABASE\DATASHEETS\ICS\DIGITAL\MICROCONTROLLER\TM4C1294NCPD.PDF
U53 = TPD4E004_SON6_0: IC 4-CH ESD PROTECTION ARRAY FOR HIGH SPEED DATA INTERFACE SON6; Chkd/date: MANIRAJA/100320; Crtd /date: MUDDU/010310; Custom_Duty: 15%; Customs_HS_Code: 85423100; Distributor_name: DIGIKEY; Distributor_part_number: 296-23618-1-ND; Footprint Path: Y:\MIS_DATABASE\Library\ALTIUM_TOOL\PCB_FOOTPRINTS\Altium_Footprint_Lib.PcbLib; Height: 0.60MM; Library Path: Y:\MIS_DATABASE\Library\ALTIUM_TOOL\SCHEMATICS_PARTS\MS_MISCINTERFACE_Library.schlib; Library Ref: TPD4E004_SON6; Mfr_name: TEXAS INSTRUMENTS; Mistral Part No: 141010020012-R; Package: SON6; Part_type: ICS\INTERFACE; Project: BUG_BASE-II; RoHS: RoHS; Temperature: -40°C+85°C; Tolerance: NA; Voltage: NA; Wattage: NA; Weight: 3.2mg; Datasheet: Y:\MIS_DATABASE\DATASHEETS\ICS\INTERFACE\TPD4E004-SER.PDF
U54 = ISO7221XD_SOIC8: IC DUAL-CHANNEL DIGITAL ISOLATOR SOIC8; Chkd/date: MANIRAJA/141021; Crtd /date: ALVY/131021; Custom_Duty: 15%; Customs_HS_Code: 85423100; Distributor_name: DIGIKEY; Distributor_part_number: 296-21956-1-ND; Footprint Path: Y:\MIS_DATABASE\Library\ALTIUM_TOOL\PCB_FOOTPRINTS\Altium_Footprint_Lib.PcbLib; Height: 1.75MM; Library Path: Y:\MIS_DATABASE\Library\ALTIUM_TOOL\SCHEMATICS_PARTS\MS_MISC_Library.schlib; Mfr_name: TEXAS INSTRUMENTS; Mistral Part No: 141021100003-R; Package: SOIC8; Part_type: ICS\DIGITAL\ISOLATOR; Project: ENEKOM_SMART SENSOR SYSTEM; RoHS: RoHS; Temperature: -40°C+125°C; Tolerance: NA; Voltage: NA; Wattage: NA; Weight: 540mg; Datasheet: Y:\MIS_DATABASE\DATASHEETS\ICS\MISC\ISO722XXD.PDF
U55 = LM4040B25IDCKR_SC70-5: IC PRECISION MICROPOWER SHUNT VOLTAGE REFERENCE SC70-5; Automotive Alternate_mfr_name: TEXAS INSTRUMENTS; Automotive Alternate_mfr_part_number: TL4050B25QDCKRQ1; Chkd/date: MANIRAJA/230817; Crtd /date: MANIRAJA/230817; Custom_Duty: 15%; Customs_HS_Code: 85423100; Distributor_name: DIGIKEY; Distributor_part_number: 296-20873-1-ND; Height: 1.10MM; Mfr_name: TEXAS INSTRUMENTS; Mistral Part No: 142017080015-R; Package: SC70-5; Part_type: ICS\POWER\VOLTAGE REGULATOR; Project: TI_MAXIE_CPB; RoHS: RoHS; Temperature: -40°C+85°C; Tolerance: NA; Voltage: NA; Wattage: NA; Weight: 30mg; Datasheet: Y:\MIS_DATABASE\DATASHEETS\ICS\POWER\LM4040B25I.PDF
Y2 = CRY4_13: CRY 16.000MHz SMD; Chkd/date: MANIRAJA/230817; Crtd /date: MANIRAJA/230817; Custom_Duty: 24%; Customs_HS_Code: 85439000; Distributor_name: DIGIKEY; Distributor_part_number: 644-1157-1-ND; Height: 0.90MM; Mfr_name: NDK; Mfr_part_number: NX3225GA-16.000M-STD-CRG-1; Mistral Part No: 130017080024-R; Package: SMD; Part_type: CRYSTAL; Project: TI_MAXIE_CPB; RoHS: RoHS; Temperature: -40°C+85°C; Tolerance: NA; Voltage: NA; Wattage: NA; Weight: NA; Datasheet: Y:\MIS_DATABASE\DATASHEETS\MISC\CRY_OSC\NX3225GA.PDF
C279 C281-C284 = CAP: CAP CERAMIC 0.1uF 50V 10% X7R 0402; Chkd/date: MANIRAJA/261020; Crtd /date: ALVY/211020; Custom_Duty: 15%; Customs_HS_Code: 85322990; Distributor_name: DIGIKEY; Distributor_part_number: 490-10700-1-ND; Footprint Path: Y:\MIS_DATABASE\Library\ALTIUM_TOOL\PCB_FOOTPRINTS\Altium_Footprint_Lib.PcbLib; Height: 0.55MM; Library Path: Y:\MIS_DATABASE\Library\ALTIUM_TOOL\SCHEMATICS_PARTS\MS_DISCRETE_Library.schlib; Mfr_name: MURATA; Mfr_part_number: GRM155R71H104KE14D; Mistral Part No: 120011100014-R; Package: 0402; Part_type: CAPACITORS\CERAMIC; Project: J7_CP; RoHS: RoHS; Temperature: -55°C+125°C; Tolerance: 10%; Voltage: 50V; Wattage: NA; Weight: 3.1mg; Datasheet: Y:\MIS_DATABASE\DATASHEETS\CAPACITORS\GRM155R71H104KE14.PDF
C280 C285 C288 C349 = CAP: CAP CERAMIC 4.7uF 10V 20% X5R 0402; Chkd/date: MANIRAJA/110718; Crtd /date: ALVY/110718; Custom_Duty: 15%; Customs_HS_Code: 85322990; Distributor_name: DIGIKEY; Distributor_part_number: 490-14306-1-ND; Footprint Path: Y:\MIS_DATABASE\Library\ALTIUM_TOOL\PCB_FOOTPRINTS\Altium_Footprint_Lib.PcbLib; Height: 0.65MM; Library Path: Y:\MIS_DATABASE\Library\ALTIUM_TOOL\SCHEMATICS_PARTS\MS_DISCRETE_Library.schlib; Mfr_name: MURATA; Mfr_part_number: GRM155R61A475MEAAD; Mistral Part No: 120012060002-R; Package: 0402; Part_type: CAPACITORS\CERAMIC; Project: TI_J7SVB_PCIE_ADD-ON-CARD; RoHS: RoHS; Temperature: -55°C+85°C; Tolerance: 20%; Voltage: 10V; Wattage: NA; Weight: 14mg; Datasheet: Y:\MIS_DATABASE\DATASHEETS\CAPACITORS\GRM155R61A475MEAAD.PDF
C286 C287 C289 C350 = CAP: CAP CERAMIC 0.1uF 10V 10% X5R 0201; Chkd/date: VASANTHA/061216; Crtd /date: MUDDU/190810; Custom_Duty: 15%; Customs_HS_Code: 85322990; Distributor_name: DIGIKEY; Distributor_part_number: 490-5881-1-ND; Footprint Path: Y:\MIS_DATABASE\Library\ALTIUM_TOOL\PCB_FOOTPRINTS\Altium_Footprint_Lib.PcbLib; Height: 0.33MM; Library Path: Y:\MIS_DATABASE\Library\ALTIUM_TOOL\SCHEMATICS_PARTS\MS_DISCRETE_Library.schlib; Mfr_name: MURATA; Mfr_part_number: GRM033R61A104KE15D; Mistral Part No: 120009050017-R; Package: 0201; Part_type: CAPACITORS\CERAMIC; Project: PB_BUGBASE; RoHS: RoHS; Temperature: -55°C+85°C; Tolerance: 10%; Voltage: 10V; Wattage: NA; Weight: 0.33mg; Datasheet: Y:\MIS_DATABASE\DATASHEETS\CAPACITORS\MURATA-GXX-SER_NOV17.PDF
C290-C309 = CAP: CAP CERAMIC 330pF 50V 5% C0G(NP0) 0402; Chkd/date: MANIRAJA/130617; Crtd /date: MAZHAR/221206; Custom_Duty: 15%; Customs_HS_Code: 85322990; Distributor_name: DIGIKEY; Distributor_part_number: 490-1295-1-ND; Footprint Path: Y:\MIS_DATABASE\Library\ALTIUM_TOOL\PCB_FOOTPRINTS\Altium_Footprint_Lib.PcbLib; Height: 0.55MM; Library Path: Y:\MIS_DATABASE\Library\ALTIUM_TOOL\SCHEMATICS_PARTS\MS_DISCRETE_Library.schlib; Mfr_name: MURATA; Mfr_part_number: GRM1555C1H331JA01D; Mistral Part No: 120009030375-R; Package: 0402; Part_type: CAPACITORS\CERAMIC; Project: ADR1B; RoHS: RoHS; Temperature: -55°C+125°C; Tolerance: 5%; Voltage: 50V; Wattage: NA; Weight: 6mg; Datasheet: Y:\MIS_DATABASE\DATASHEETS\CAPACITORS\MURATA-GXX-SER_NOV17.PDF
FL7 = EMIFILTER_IND: PASSIVE FILTER EMI 100E 2A 0603; Chkd/date: BAVISH/170811; Crtd /date: CHAITHANYA/170811; Custom_Duty: 24%; Customs_HS_Code: 85437099; Distributor_name: DIGIKEY; Distributor_part_number: BLM18EG101TN1D-ND; Footprint Path: Y:\MIS_DATABASE\Library\ALTIUM_TOOL\PCB_FOOTPRINTS\Altium_Footprint_Lib.PcbLib; Height: 0.65MM; Library Path: Y:\MIS_DATABASE\Library\ALTIUM_TOOL\SCHEMATICS_PARTS\MS_FILTER_Library.schlib; Mfr_name: MURATA; Mfr_part_number: BLM18EG101TN1D; Mistral Part No: 130011080028-R; Package: 0603; Part_type: FILTER; Project: CPCI3GADC_CARD; RoHS: RoHS; Temperature: -55°C+125°C; Tolerance: NA; Voltage: NA; Wattage: NA; Weight: NA; Datasheet: Y:\MIS_DATABASE\DATASHEETS\DISCRETES\INDUCTORS\BLM18E.PDF
J14 = HEADER_2X2: CON HDR 2X2 2.54MM PITCH ST TH; Chkd/date: MANIRAJA/091117; Crtd /date: MANIRAJA/091117; Custom_Duty: 24%; Customs_HS_Code: 85369090; Distributor_name: DIGIKEY; Distributor_part_number: A121466-ND; Height: 8.21MM; Mfr_name: TE CONNECTIVITY; Mfr_part_number: 5-146256-2; Mistral Part No: 150017110014-R; Package: THRU-HOLE; Part_type: CONNECTOR\HEADERS; Project: TI_SVB_MAXWELL_DUT; RoHS: RoHS; Temperature: -65°C+105°C; Tolerance: NA; Voltage: NA; Wattage: NA; Weight: 299mg; Datasheet: Y:\MIS_DATABASE\DATASHEETS\CONNECTORS\146256-SERIES.PDF
R401-R404 R1648 R1649 = RESISTOR: RES 0E 1/10W JUMPER 0402; Chkd/date: VASANTHA/061216; Crtd /date: NAVEED/201014; Custom_Duty: 15%; Customs_HS_Code: 85332119; Distributor_name: DIGIKEY; Distributor_part_number: P0.0JCT-ND; Footprint Path: Y:\MIS_DATABASE\Library\ALTIUM_TOOL\PCB_FOOTPRINTS\Altium_Footprint_Lib.PcbLib; Height: 0.40MM; IBISSP_MODLES: VALUE REPEATING 2 TIME; Library Path: Y:\MIS_DATABASE\Library\ALTIUM_TOOL\SCHEMATICS_PARTS\MS_DISCRETE_Library.schlib; Mfr_name: PANASONIC-ECG; Mfr_part_number: ERJ-2GE0R00X; Mistral Part No: 110018030052-R; Package: 0402; Part_type: RESISTORS\FIXED; Project: AEGIS POM; RoHS: RoHS; Temperature: -55°C+155°C; Tolerance: NA; Voltage: NA; Wattage: 1/10W; Weight: 0.8mg; Datasheet: Y:\MIS_DATABASE\DATASHEETS\RESISTORS\PAN-ERJSER_NOV17.PDF
SW7 SW8 SW13 = SWTACT_CAS-120TA: SWITCH TACT SPST SMD; Chkd/date: MAZHAR/221108; Crtd /date: USMAN/171008; Custom_Duty: 24%; Customs_HS_Code: 85369090; Distributor_name: DIGIKEY; Distributor_part_number: CAS120JCT-ND; Height: 2.50MM; Mfr_name: COPAL ELECTRONICS; Mistral Part No: 130009030342; Package: SMD; Part_type: ELECTRO-MECHANICAL\SWITCH; Project: SMART VIEW_IP CAMERA; Datasheet: Y:\MIS_DATABASE\DATASHEETS\MISC\SWITCHES\CAS-XX.PDF
SW9 = SWTACT_CAS-D20TA: SWITCH TACT SPDT SMD; Chkd/date: VASANTHA/281215; Crtd /date: VASANTHA/281215; Custom_Duty: 24%; Customs_HS_Code: 85369090; Distributor_name: DIGIKEY; Distributor_part_number: CASD20JCT-ND; Height: 2.50MM; Mfr_name: COPAL ELECTRONICS; Mistral Part No: 130015120021-R; Package: SMD; Part_type: ELECTRO-MECHANICAL\SWITCH; Project: TI_VLAN_SWITCH; RoHS: RoHS; Temperature: -40°C+85°C; Tolerance: NA; Voltage: NA; Wattage: NA; Weight: NA; Datasheet: Y:\MIS_DATABASE\DATASHEETS\MISC\SWITCHES\CAS-XX.PDF
U61-U65 = TPD4E001_SOT23-6: IC 4CH ESD-PROTECTION ARRAY SOT23-6; Chkd/date: USMAN/250112; Crtd /date: CHAITHANYA/190112; Custom_Duty: 15%; Customs_HS_Code: 85423100; Distributor_name: DIGIKEY; Distributor_part_number: 296-28203-1-ND; Height: 1.60MM; Mfr_name: TEXAS INSTRUMENTS; Mistral Part No: 141012010005-R; Part_type: ICS\INTERFACE; Project: DM385EVM_BASE-BOARD; RoHS: RoHS; Temperature: NA; Tolerance: NA; Voltage: NA; Wattage: NA; Weight: NA; Datasheet: Y:\MIS_DATABASE\DATASHEETS\ICS\INTERFACE\TPD4E001-SER.PDF
U67 = OPA4350EA_SSOP16: IC HIGH-SPEED RAIL-TO-RAIL OPERATIONAL AMPLIFIERS MICROAMPLIFIER SERIES SSOP16; Crtd /date: ALVY/190321; Custom_Duty: 15%; Customs_HS_Code: 85423100; Distributor_name: DIGIKEY; Distributor_part_number: OPA4350EACT-ND; Footprint Path: Y:\MIS_DATABASE\Library\ALTIUM_TOOL\PCB_FOOTPRINTS\Altium_Footprint_Lib.PcbLib; Height: 1.75MM; Library Path: Y:\MIS_DATABASE\Library\ALTIUM_TOOL\SCHEMATICS_PARTS\MS_OPAMP_Library.schlib; Mfr_name: TEXAS INSTRUMENTS; Mistral Part No: 140121030011-R; Package: SSOP16; Part_type: ICS\ANALOG\OPAMP; Project: TI_AM263x_CC; RoHS: RoHS; Temperature: -40°C+85°C; Tolerance: NA; Voltage: NA; Wattage: NA; Weight: 73.8mg; Datasheet: Y:\MIS_DATABASE\DATASHEETS\ICS\OPAMP\OPAX350.PDF

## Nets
DGND: C265.2 C279.2 C280.2 C281.2 C282.2 C283.2 C284.2 C290.2 C291.2 C292.2 C293.2 C294.2 C295.2 C296.2 C297.2 C298.2 C299.2 C300.2 C301.2 C302.2 C303.2 C304.2 C305.2 C306.2 C307.2 C308.2 C309.2 J14.3 J14.4 R396.2 R397.2 R398.2 R399.2 R400.2 R403.1 R404.1 R1649.1 U54.4(GND1) U61.2(GND) U62.2(GND) U63.2(GND) U64.2(GND) U65.2(GND) U67.13(-V) ; also on sheet 1 2 3 4 6 7 8 9 10 11 12 13 14 15 24 25 26 27 28 29 30 32 33
V3V3_XDS_FB: C248.2 R332.2 R333.1 U51.5(NR/FB)
VBAT_XDS: C262.1 R334.2 U52.68(VBAT)
VBUS_XDS110: C256.1 J13.1(VBUS) R339.2 R340.1 TP66.1(TP) U51.1(IN1) U51.2(IN2) U51.8(EN) U53.6(VCC)
VCC3V3_XDS: C248.1 C249.1 C250.1 C251.1 C252.1 C253.1 C254.1 C255.1 C257.1 C258.1 C266.1 R332.1 R334.1 R345.2 R346.2 R347.2 R348.2 R353.1 R354.1 R356.1 R357.1 TP67.1(TP) U51.3(OUT1) U51.4(OUT2) U52.7(VDD) U52.8(VDDA) U52.16(VDD) U52.26(VDD) U52.28(VDD) U52.39(VDD) U52.47(VDD) U52.51(VDD) U52.52(VDD) U52.69(VDD) U52.79(VDD) U52.90(VDD) U52.101(VDD) U52.113(VDD) U52.122(VDD) U54.8(VCC2) ; also on sheet 3 27 28
VCC_1V8_LDO4: SW7.1 ; also on sheet 30
VDDA_IO_1V8: SW8.1 ; also on sheet 8
VDDA_IO_3V3: C281.1 C282.1 C283.1 C284.1 FL7.2 U61.5(VCC) U62.5(VCC) U63.5(VCC) U64.5(VCC) U65.5(VCC) U67.4(+V) ; also on sheet 2 6
VDDC_1V2_XDS: C259.1 C260.1 C261.1 U52.87(VDDC) U52.115(VDDC)
ADC4_AIN0/ADC_CAL0/ADC_R0_AIN0: C306.1 U61.4(IO3) ; also on sheet 6
ADC4_AIN1/ADC_CAL1/ADC_R0_AIN1: C307.1 U61.6(IO4) ; also on sheet 6
ADC_CAL0: U1.U16(ADC_CAL0) ; also on sheet 2
ADC_CAL1: U1.T15(ADC_CAL1) ; also on sheet 2
ADC_CAL2: J14.1 U1.U17(ADC_CAL2) U65.4(IO3)
ADC_CAL3: J14.2 U1.N17(ADC_CAL3) U65.6(IO4)
ADC_DAC-VREF: SW7.2(COM) U67.3(+INA) U67.5(+INB) U67.12(+INC) U67.14(+IND)
ADC_R0_AIN0: U1.T18(ADC_R0_AIN0) ; also on sheet 2
ADC_R0_AIN1: U1.T16(ADC_R0_AIN1) ; also on sheet 2
ADC_R0_AIN2: U1.U18(ADC_R0_AIN2) ; also on sheet 2
ADC_R0_AIN3: U1.T17(ADC_R0_AIN3) ; also on sheet 2
ADC_R1_AIN0: U1.R16(ADC_R1_AIN0) ; also on sheet 2
ADC_R1_AIN1: U1.R18(ADC_R1_AIN1) ; also on sheet 2
ADC_R1_AIN2: U1.P18(ADC_R1_AIN2) ; also on sheet 2
ADC_R1_AIN3: U1.P17(ADC_R1_AIN3) ; also on sheet 2
ADC_VREF1: SW9.3 U67.1(OUTA) U67.2(-INA)
ADC_VREF2: SW9.6 U67.6(-INB) U67.7(OUTB)
ADC_VREF3: SW13.3 U67.15(-IND) U67.16(OUTD)
ADC_VREFHI_G0_G1: R401.2 SW9.2
ADC_VREFHI_G0_G1_R: C285.1 C286.1 C287.1 R401.1 U1.V10(ADC_VREFHI_G1) U1.V14(ADC_VREFHI_G0)
ADC_VREFHI_G2: R402.2 SW9.5
ADC_VREFHI_G2_R: C288.1 C289.1 R402.1 U1.V6(ADC_VREFHI_G2)
ADC_VREFHI_G3: R1648.1 SW13.2(COM)
ADC_VREFHI_G3_R: C349.1 C350.1 R1648.2 U1.V17(ADC_VREFHI_G3)
AM263_ADC_VREFLO_1: C285.2 C286.2 C287.2 R404.2 U1.V11(ADC_VREFLO_G1) U1.V13(ADC_VREFLO_G0)
AM263_ADC_VREFLO_2: C288.2 C289.2 R403.2 U1.V7(ADC_VREFLO_G2)
AM263_ADC_VREFLO_3: C349.2 C350.2 R1649.2 U1.V16(ADC_VREFLO_G3)
AM263_DAC_VREF: SW8.3 U67.10(OUTC) U67.11(-INC)
AM263_DAC_VREF0: C279.1 C280.1 SW8.2(COM) U1.T6(DAC_VREF1) U1.T13(DAC_VREF0)
BOOTMODE_XDS_I2C_SCL: U52.49(PG0) ; also on sheet 3
BOOTMODE_XDS_I2C_SDA: U52.50(PG1) ; also on sheet 3
HSEC_ADC0_AIN0: U1.V15(ADC0_AIN0) ; also on sheet 6
HSEC_ADC0_AIN0/DAC_OUT: C290.1 U61.1(IO1) ; also on sheet 6
HSEC_ADC0_AIN1: U1.U15(ADC0_AIN1) ; also on sheet 6
HSEC_ADC0_AIN1/DAC_OUT: C291.1 U61.3(IO2) ; also on sheet 6
HSEC_ADC0_AIN2: C292.1 U1.T14(ADC0_AIN2) U62.6(IO4) ; also on sheet 6
HSEC_ADC0_AIN3: C293.1 U1.U14(ADC0_AIN3) U62.4(IO3) ; also on sheet 6
HSEC_ADC0_AIN4: C294.1 U1.U13(ADC0_AIN4) U63.6(IO4) ; also on sheet 6
HSEC_ADC0_AIN5: C295.1 U1.R14(ADC0_AIN5) U63.4(IO3) ; also on sheet 6
HSEC_ADC1_AIN0: C296.1 U1.T11(ADC1_AIN0) U62.1(IO1) ; also on sheet 6
HSEC_ADC1_AIN1: C297.1 U1.U11(ADC1_AIN1) U62.3(IO2) ; also on sheet 6
HSEC_ADC1_AIN2: C298.1 U1.T12(ADC1_AIN2) U63.1(IO1) ; also on sheet 6
HSEC_ADC1_AIN3: C299.1 U1.V12(ADC1_AIN3) U63.3(IO2) ; also on sheet 6
HSEC_ADC1_AIN4: C302.1 U1.U12(ADC1_AIN4) U64.1(IO1) ; also on sheet 6
HSEC_ADC1_AIN5: C303.1 U1.R12(ADC1_AIN5) U64.3(IO2) ; also on sheet 6
HSEC_ADC2_AIN0: U1.R10(ADC2_AIN0) ; also on sheet 2
HSEC_ADC2_AIN1: U1.T10(ADC2_AIN1) ; also on sheet 2
HSEC_ADC2_AIN2: C304.1 C308.1 U1.U10(ADC2_AIN2) U65.1(IO1) ; also on sheet 6
HSEC_ADC2_AIN3: C305.1 C309.1 U1.T9(ADC2_AIN3) U65.3(IO2) ; also on sheet 6
HSEC_ADC3_AIN0: U1.U7(ADC3_AIN0) ; also on sheet 2
HSEC_ADC3_AIN1: U1.U8(ADC3_AIN1) ; also on sheet 2
HSEC_ADC3_AIN2: U1.T7(ADC3_AIN2) ; also on sheet 2
HSEC_ADC3_AIN3: U1.R7(ADC3_AIN3) ; also on sheet 2
HSEC_ADC3_AIN4: C300.1 U1.V8(ADC3_AIN4) U64.6(IO4) ; also on sheet 6
HSEC_ADC3_AIN5: C301.1 U1.U9(ADC3_AIN5) U64.4(IO3) ; also on sheet 6
HSEC_ADC4_AIN0: U1.U6(ADC4_AIN0) ; also on sheet 6
HSEC_ADC4_AIN1: U1.V5(ADC4_AIN1) ; also on sheet 6
HSEC_ADC-VREFHI: SW7.3 ; also on sheet 6
HSEC_DAC_OUT: U1.T5(DAC_OUT) ; also on sheet 6
OSC0: C269.2 U52.88(OSC0) Y2.1
OSC1: C270.2 U52.89(OSC1) Y2.3
PMIC_DIAG_OUT: U1.V4(ADC4_AIN2) ; also on sheet 30
SOC_XDS_I2C2_SCL: U52.82(PL1) ; also on sheet 28
SOC_XDS_I2C2_SDA: U52.81(PL0) ; also on sheet 28
TA_GPIO1_XDS: U52.74(PM4) ; also on sheet 3
TA_GPIO2_XDS: U52.73(PM5) ; also on sheet 3
TA_GPIO3_XDS: U52.72(PM6) ; also on sheet 3
TA_GPIO4_XDS: U52.71(PM7) ; also on sheet 3
TA_PORZn_XDS: U52.77(PM1) ; also on sheet 3
TA_POWERDOWNz_XDS: U52.78(PM0) ; also on sheet 3
TA_RESETz_XDS: U52.76(PM2) ; also on sheet 3
TM4C129_RST#: R353.2 R355.1 TP73.1(TP) U52.70(~{RST})
TM4C129_TCK: TP68.1(TP) U52.100(PC0/TCK/SWCLK)
TM4C129_TDI: TP70.1(TP) U52.98(PC2/TDI)
TM4C129_TDO: TP71.1(TP) U52.97(PC3/TDO/SWO)
TM4C129_TMS: TP69.1(TP) U52.99(PC1/TMS/SWDIO)
UART0_RXD: R344.1 ; also on sheet 26
UART0_TXD: U54.3(INB) ; also on sheet 26
USB_XDS110_ID: J13.4(ID) R338.2 U53.4(IO3)
VSYS_3V3_LDO1: C265.1 FL7.1 U54.1(VCC1) ; also on sheet 1 6 7 9 10 11 12 13 14 15 24 26 27 28 29 30 32 33
XDS110_EMU0: R357.2 U52.42(PF0)
XDS110_EMU1: R356.2 U52.43(PF1)
XDS110_PROG_STAZ1: R342.2 U52.4(PD3/AIN12)
XDS110_PROG_STAZ2: R343.1 U52.3(PD2/AIN13)
XDS110_TCK: U52.35(PA2/SSI0CLK) ; also on sheet 27
XDS110_TDI: U52.38(PA5/SSI0XDAT1) ; also on sheet 27
XDS110_TDO: U52.37(PA4/SSI0XDAT0) ; also on sheet 27
XDS110_TMS: U52.36(PA3/SSI0FSS) ; also on sheet 27
XDS110_TRST#: R337.1 U52.40(PA6)
XDS110_UART0_RXD: U52.33(PA0/U0RX) U54.6(OUTB)
XDS110_UART0_TXD: R336.1 U54.7(INA)
XDS110_VBUS_DET: R340.2 R341.1 U52.1(PD0/AIN15)
XDS_GND: C249.2 C250.2 C251.2 C252.2 C253.2 C254.2 C255.2 C256.2 C257.2 C258.2 C259.2 C260.2 C261.2 C262.2 C263.2 C264.2 C266.2 C267.2 C268.2 C269.1 C270.1 J13.5(GND) LD9.1(CATHODE) LD10.1(CATHODE) R333.2 R335.2 R337.2 R341.2 R349.1 R350.1 R351.1 R352.1 R355.2 R358.2 TP74.1(TP) U51.6(GND) U51.9(PAD) U52.10(GNDA) U52.17(GND) U52.48(GND) U52.55(GND) U52.58(GND) U52.64(~{WAKE}) U52.66(XOSC0) U52.80(GND) U52.114(GND) U53.3(GND) U54.5(GND2) U55.1(ANODE) Y2.2 Y2.4 ; also on sheet 3 27 28
XDS_RBIAS: R358.1 U52.59(RBAIS)
XDS_SHIELD: C263.1 J13.6(SH1) J13.7(SH2) J13.8(SH3) J13.9(SH4) J13.10(SH5) J13.11(SH6) R335.1
XDS_USB_D_N: J13.2(D-) U52.93(PL7/USB0DM) U53.1(IO1)
XDS_USB_D_P: J13.3(D+) U52.94(PL6/USB0DP) U53.2(IO2)
XDS_USB_ID: R338.1 U52.95(PB0/USB0ID)
XDS_VREF: C267.1 C268.1 R354.2 U52.9(VREFA+) U55.3(CATHODE)
N23200398: C264.1 R339.1 U52.96(PB1/USB0VBUS)
N23200423: R345.1 R349.2 U52.60(PK7)
N23200491: LD10.2(ANODE) R343.2
N23200507: R348.1 R352.2 U52.63(PK4)
N23200509: R346.1 R350.2 U52.61(PK6)
N23200516: R347.1 R351.2 U52.62(PK5)
N23200616: LD9.2(ANODE) R342.1
N32845712: R396.1 U1.V9(ADC2_AIN4)
N32845714: R397.1 U1.T8(ADC2_AIN5)
N32914108: R336.2 U52.34(PA1/U0TX)
N33221101: R400.1 U1.U4(ADC4_AIN5)
N33221125: R398.1 U1.U5(ADC4_AIN3)
N33221128: R399.1 U1.V3(ADC4_AIN4)
N33884757: R344.2 U54.2(OUTA)
N34660939: TP72.1(TP) U52.75(PM3)

Not connected (* = marked no-connect by the designer): SW9 1* 4*; SW13 1*; U1 P15(NC); U51 7(NC)*; U52 2(PD1/AIN14)* 5(PQ0)* 6(PQ1)* 11(PQ2)* 12(PE3/AIN0)* 13(PE2/AIN1)* 14(PE1/AIN2)* 15(PE0/AIN3)* 18(PK0/AIN16)* 19(PK1/AIN17)* 20(PK2/AIN18)* 21(PK3/AIN19)* 22(PC7/C0-)* 23(PC6/C0+)* 24(PC5/C1+)* 25(PC4/C1-)* 27(PQ3)* 29(PH0)* 30(PH1)* 31(PH2)* 32(PH3)* 41(PA7)* 44(PF2)* 45(PF3)* 46(PF4)* 53(EN0RXIN)* 54(EN0RXIP)* 56(EN0RX0N)* 57(EN0RX0P)* 65(~{HIB})* 67(XOSC1)* 83(PL2)* 84(PL3)* 85(PL4)* 86(PL5)* 91(PB2/I2C0SCL)* 92(PB3/I2C0SDA)* 102(PQ4)* 103(PP2)* 104(PP3)* 105(PP4)* 106(PP5)* 107(PN0)* 108(PN1)* 109(PN2)* 110(PN3)* 111(PN4)* 112(PN5)* 116(PJ0)* 117(PJ1)* 118(PP0/C2+)* 119(PP1/C2-)* 120(PB5/AIN11)* 121(PB4/AIN10)* 123(PE4/AIN9)* 124(PE5/AIN8)* 125(PD4/AIN7)* 126(PD5/AIN6)* 127(PD6/AIN5)* 128(PD7/AIN4)*; U53 5(IO4)*; U55 2(NC1)* 4(NC2)* 5(NC3)*; U67 8(NC1)* 9(NC2)*

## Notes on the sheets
sheet 16
- SOC- ADC & DAC Interface
- CAD NOTE: Place the ESDs close to connector
- SOC- DAC Interface
- SILK "VREF"
- REF VOLTAGE SELECTION
- SW POSITION
- SUPPLY SELECTION
- PIN 1-2
- ON BOARD REF IS
  SELECTED
- HSEC SUPPLY IS SELECTED
- PIN 2-3
- SILK "DAC VREF"
- DAC REF VOLTAGE SELECTION
- SW POSITION
- SUPPLY SELECTION
- DIAG_OUT - PMIC Analog/Digital
  Diagnostic Output to MCU
- PIN 1-2
- Allows AM263P on-die
  LDO reference (Routed n PCB)
- selects output of VREF switch
- PIN 2-3
- SILK
  "ADC VREF"
- CAD NOTE: Place the CAPs close to each other
- CAD NOTE: - Place decoupling at BGA between
  VREF and GND
  Place GND short as close as possible
  to BGA and decoupling
- ADC REF VOLTAGE SELECTION
- SW POSITION
- SUPPLY SELECTION
- CAD NOTE: Place the 2x2 header close to VSSA plane
- OPEN - Allows AM263P on-die
  LDO reference (routed on-die)
- PIN 1-2
- CAD NOTE: Place the CAPs close to the connector
- selects output of VREF switch
- PIN 2-3
- PIN 4-5
- OPEN - Allows AM263P on-die
  LDO reference (routed on-die)
- PIN 5-6
- selects output of VREF switch
- ADC REF VOLTAGE SELECTION
- SW POSITION
- SUPPLY SELECTION
- PIN 1-2
- OPEN - Allows AM263P on-die
  LDO reference (routed on-die)
- PIN 2-3
- selects output of VREF switch
sheet 17
- XDS110 DEBUGGER
- Silkscreen "XDS110"
- 90E
- UART0 BUFFER
- GREEN
- RED
- Set the unique ID
  of the debugger
- EMU signals
